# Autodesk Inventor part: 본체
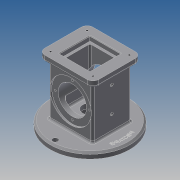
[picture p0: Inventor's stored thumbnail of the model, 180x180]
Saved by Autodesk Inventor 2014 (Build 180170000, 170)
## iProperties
Created: 2019-08
Part Number: 본체
Material: Generic
Document SubType Name: Modeling
Designer: kb542-18
Density: 1 g/cm^3
Appearance: Default
Author: kb542-18
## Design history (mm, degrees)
sketch "스케치1"
  geometry: C1 r 67.5 at (0, 0); 1 further point
  constraints: 1 centre point, 1 coincident
  dimensions: "d0" = 135 diameter of C1
extrude "돌출1" new body sketch "스케치1" distance "d1" = 10; taper "d2" = 0 deg
sketch "스케치2"
  geometry: C1 r 67.5 at (0, 0) reference; 3 further points
  constraints: 2 vertical alignment, 1 horizontal alignment
  dimensions: "d3" = 59 distance of C1.centre point (0, 59); "d4" = 59 distance of point (-59, 0) C1.centre; "d5" = 59 distance of point (0, -59) C1.centre
hole "구멍1" sketch "스케치2" at (0, 59), (-59, 0), (0, -59) diameter "d6" = 9; stored, may be unused: countersink angle "d10" = 90 deg, drill point angle "d12" = 118 deg; dims "d7" = 6, "d8" = 4, "d9" = 2, "d11" = 8
sketch "스케치3"
  geometry: L1 (37, -33)-(-37, -33); L2 (-37, -33)-(-37, 33); L3 (-37, 33)-(37, 33); L4 (37, 33)-(37, -33); L5 (37, -33)-(-37, 33); L6 (-37, -33)-(37, 33); C1 r 67.5 at (0, 0) reference
  constraints: 12 end point, 2 midpoint, 2 parallel, 1 horizontal, 1 perpendicular
  dimensions: "d13" = 74 distance of L2.end L3.end; "d14" = 66 distance of L1.end L2.end
extrude "돌출2" join sketch "스케치3" distance "d15" = 98; taper "d16" = 0 deg
sketch "스케치4"
  geometry: L1 (46, -41)-(-46, -41); L2 (-46, -41)-(-46, 41); L3 (-46, 41)-(46, 41); L4 (46, 41)-(46, -41); L5 (46, -41)-(-46, 41); L6 (-46, -41)-(46, 41); 1 further point
  constraints: 12 end point, 2 midpoint, 2 parallel, 1 horizontal, 1 perpendicular
  dimensions: "d17" = 92 distance of L2.end L3.end; "d18" = 82 distance of L3.end L1.start
extrude "돌출3" join sketch "스케치4" distance "d19" = 10; taper "d20" = 0 deg
chamfer "모따기1" distance "d21" = 3; stored, may be unused: second distance "d22" = 2, angle "d23" = 45 deg
fillet "모깎기1" dims "d35" = 10
sketch "스케치6"
  geometry: C1 r 12.5 at (0, 0); 1 further point
  constraints: 1 centre point, 1 coincident
  dimensions: "d36" = 25 diameter of C1
extrude "돌출4" cut sketch "스케치6" stored distance "d37" = 10; taper "d38" = 0 deg
sketch "스케치7"
  geometry: C1 r 12.5 at (0, 0) reference; C2 r 67.5 at (0, 0) reference; C3 r 25 at (0, 0)
  constraints: 1 centre point, 1 coincident
  dimensions: "d39" = 50 diameter of C3
extrude "돌출5" cut sketch "스케치7" distance "d40" = 18; taper "d41" = 0 deg
sketch "스케치10"
  geometry: L1 (95.883, -3)-(95.883, -10) reference; L2 (95.883, -10)-(-21.883, -10) reference; L3 (-21.883, -10)-(-21.883, -3) reference; L4 (-18.419, 0)-(0, 0) reference; L5 (0, 0)-(74, 0) reference; L6 (74, 0)-(92.419, 0) reference; L7 (0, 0)-(0, 88) reference; L8 (-8.798, 88)-(-8.798, 98) reference; L9 (82.798, 98)-(82.798, 88) reference; L10 (74, 88)-(74, 0) reference; L11 (0, 88)-(-8.798, 88) reference; L12 (-8.798, 98)-(82.798, 98) reference; L13 (82.798, 88)-(74, 88) reference; L14 (74, 88)-(0, 88) reference; C1 r 35 at (37, 44); 2 further points
  constraints: 1 centre point, 1 midpoint, 1 vertical alignment, 2 other
  dimensions: "d50" = 70 diameter of C1; "d52" = 54 distance from line of C1.centre L2
extrude "돌출8" cut sketch "스케치10" distance "d53" = 3; taper "d54" = 0 deg
sketch "스케치11"
  geometry: C1 r 35 at (0, 0) reference; C2 r 24 at (0, 0); 1 further point
  constraints: 1 centre point, 1 coincident
  dimensions: "d55" = 48 diameter of C2
extrude "돌출9" cut sketch "스케치11" stored distance "d56" = 3; taper "d57" = 0 deg
sketch "스케치12"
  geometry: C1 r 24 at (0, 0) reference; 2 further points
  constraints: 1 vertical alignment
  dimensions: "d58" = 29 distance of C1.centre point (0, 29)
hole "구멍3" sketch "스케치12" at (0, 29) diameter "d59" = 3.242; stored, may be unused: countersink angle "d63" = 90 deg, drill point angle "d65" = 118 deg; dims "d60" = 4, "d61" = 4, "d62" = 2, "d64" = 6
sketch "스케치14"
  geometry: C1 r 64.5 at (0, 0) reference; C2 r 59 at (0, 0)
  constraints: 1 centre point, 1 coincident, 1 other
  dimensions: "d92" = 118 diameter of C2
feature "엠보싱1" sketch "스케치14" dims "d15" = 98, "d16" = 0, "d93" = 0.5, "d94" = 0
fillet "모깎기2" dims "d95" = 3
fillet "모깎기3" dims "d96" = 3
fillet "모깎기4" dims "d97" = 3
sketch "스케치15"
  geometry: L1 (26, -26)-(-26, -26); L2 (-26, -26)-(-26, 26); L3 (-26, 26)-(26, 26); L4 (26, 26)-(26, -26); L5 (26, -26)-(-26, 26); L6 (-26, -26)-(26, 26); C1 r 12.5 at (0, 0) reference
  constraints: 12 end point, 2 midpoint, 2 parallel, 1 horizontal, 1 perpendicular
  dimensions: "d103" = 52 distance of L2.end L3.end; "d104" = 52 distance of L3.end L1.start
extrude "돌출10" cut sketch "스케치15" distance "d105" = 8; taper "d106" = 0 deg
sketch "스케치16"
  geometry: L1 (22, -22)-(-22, -22); L2 (-22, -22)-(-22, 22); L3 (-22, 22)-(22, 22); L4 (22, 22)-(22, -22); L5 (22, -22)-(-22, 22); L6 (-22, -22)-(22, 22); C1 r 12.5 at (0, 0) reference
  constraints: 12 end point, 2 midpoint, 2 parallel, 1 horizontal, 1 perpendicular
  dimensions: "d107" = 44 distance of L2.end L3.end; "d108" = 44 distance of L1.end L2.end
extrude "돌출11" cut sketch "스케치16" distance "d109" = 74; taper "d110" = 0 deg
sketch "스케치17"
  geometry: A1 r 10 centre (36, -31) between (36, -41) and (46, -31) reference; A2 r 10 centre (36, 31) between (46, 31) and (36, 41) reference; A3 r 10 centre (-36, 31) between (-36, 41) and (-46, 31) reference; A4 r 10 centre (-36, -31) between (-46, -31) and (-36, -41) reference; 5 further points
  constraints: 4 coincident
hole "구멍7" sketch "스케치17" at (-36, 31), (36, 31), (-36, -31), (36, -31) diameter "d111" = 3.242; stored, may be unused: countersink angle "d115" = 90 deg, drill point angle "d117" = 118 deg; dims "d112" = 4, "d113" = 4, "d114" = 2, "d116" = 6
sketch "스케치18"
  geometry: L1 (0, -11.226)-(-10, -11.226) reference; L2 (-10, -11.226)-(-10, -2.552) reference; L3 (0, -0.276)-(0, -11.226) reference; L4 (0, 70.674)-(0, 59.724) reference; L5 (-10, 62)-(-10, 70.674) reference; L6 (-10, 70.674)-(0, 70.674) reference; L7 (85, -0.276)-(0, -0.276) reference; L8 (85, -0.276)-(85, 59.724) reference; L9 (88, 64.92)-(88, 82.556) reference; L10 (91, 86.18)-(98, 86.18) reference; L11 (98, 86.18)-(98, -26.732) reference; L12 (98, -26.732)-(91, -26.732) reference; L13 (88, -23.108)-(88, -5.472) reference; L14 (85, 59.724)-(0, 59.724) reference; L15 (-10, 0)-(-10, 59.448) reference; L16 (-10, -2.552)-(-4, -2.552) reference; L17 (-4, 0)-(-10, 0) reference; L18 (-10, 59.448)-(-4, 59.448) reference; L19 (-4, 62)-(-10, 62) reference; L20 (0, 59.724)-(0, -0.276) reference; 4 further points
  constraints: 2 horizontal alignment, 2 vertical alignment, 1 midpoint, 4 other
  dimensions: "d118" = 37 distance from line of point (61, 29.724) L11; "d119" = 43 distance of point (18, 29.724) point (61, 29.724)
  node "절단 모서리 투영3"
hole "구멍8" sketch "스케치18" diameter "d120" = 4.917; stored, may be unused: countersink angle "d124" = 90 deg, drill point angle "d126" = 118 deg; dims "d121" = 4, "d122" = 4, "d123" = 2, "d125" = 6
hole "구멍9" sketch "스케치18" diameter "d127" = 4.917; stored, may be unused: countersink angle "d131" = 90 deg, drill point angle "d133" = 118 deg; dims "d128" = 4, "d129" = 4, "d130" = 2, "d132" = 6
fillet "모깎기7" dims "d134" = 3
chamfer "모따기3" distance "d135" = 1; stored, may be unused: second distance "d136" = 2, angle "d137" = 45 deg
fillet "모깎기8" dims "d138" = 3
fillet "모깎기9" dims "d139" = 3
fillet "모깎기10" dims "d140" = 3
node "솔리드1"
mirror "대칭1"
pattern_circular "원형 패턴1" dims angle "d67" = 360 deg
mirror "대칭2"
sketch "스케치13"
  geometry: L1 (3, 89.456)-(10, 89.456) reference; L2 (10, 89.456)-(10, -23.456) reference; L3 (10, -23.456)-(3, -23.456) reference; L4 (0, -19.832)-(0, 0) reference; L5 (0, 0)-(0, 66) reference; L6 (0, 66)-(0, 85.832) reference; L7 (0, 0)-(-88, 0) reference; L8 (-88, -7.95)-(-98, -7.95) reference; L9 (-98, 73.95)-(-88, 73.95) reference; L10 (-88, 66)-(0, 66) reference; L11 (-88, 73.95)-(-88, 66) reference; L12 (-98, -7.95)-(-98, 73.95) reference; L13 (-88, 0)-(-88, -7.95) reference; L14 (-88, 66)-(-88, 0) reference; 3 further points
  constraints: 1 horizontal alignment, 1 midpoint, 2 other
node "절단 모서리 투영1"
node "절단 모서리 투영2"
